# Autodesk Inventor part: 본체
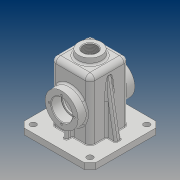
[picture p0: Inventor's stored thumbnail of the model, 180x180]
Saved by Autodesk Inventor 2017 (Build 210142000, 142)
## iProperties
Part Number: 본체
Material: 일반
Document SubType Name: Modeling
Designer: 20
Density: 1 g/cm^3
Appearance: 기본값
Mass: 292.115 g
Surface Area: 897.365 cm^2
Volume: 292.115 cm^3
Author: 20
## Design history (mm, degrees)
sketch "스케치1"
  geometry: L1 (-32.5, -32.5)-(32.5, -32.5); L2 (32.5, -32.5)-(32.5, 32.5); L3 (32.5, 32.5)-(-32.5, 32.5); L4 (-32.5, 32.5)-(-32.5, -32.5); L5 (-32.5, -32.5)-(32.5, 32.5); L6 (32.5, -32.5)-(-32.5, 32.5); 1 further point
  constraints: 12 end point, 2 midpoint, 2 parallel, 1 horizontal, 1 perpendicular
  dimensions: "d0" = 65 distance of L3.end L2.end; "d1" = 65 distance of L2.end L1.end
extrude "돌출1" new body sketch "스케치1" distance "d2" = 100; taper "d3" = 0 deg
fillet "모깎기1" dims "d4" = 8
fillet "모깎기2" dims "d5" = 8
feature "쉘1" dims "d6" = 5
sketch "스케치2"
  geometry: C1 r 20 at (0, 0); 1 further point
  constraints: 1 centre point, 1 coincident
  dimensions: "d7" = 40 diameter of C1
extrude "돌출2" join sketch "스케치2" distance "d8" = 10; taper "d9" = -5 deg
node "작업 평면1"
sketch "스케치4"
  geometry: C1 r 27.5 at (24.5, 45); 1 further point
  constraints: 1 centre point, 1 vertical alignment
  dimensions: "d14" = 55 diameter of C1; "d15" = 45 distance of C1.centre point (24.5, 0)
extrude "돌출4" join sketch "스케치4" stored distance "d16" = 10; taper "d17" = 0 deg
hole "구멍1" diameter "d20" = 30; stored, may be unused: countersink angle "d24" = 90 deg, drill point angle "d26" = 0 deg; dims "d18" = 10, "d19" = 10, "d21" = 6, "d22" = 35, "d23" = 17, "d25" = 20
sketch "스케치5"
  geometry: C1 r 27.5 at (0, 0) reference; 2 further points
  constraints: 1 vertical alignment
  dimensions: "d27" = 21 distance of C1.centre point (0, 21)
hole "구멍2" sketch "스케치5" at (0, 21) diameter "d28" = 3.242; stored, may be unused: countersink angle "d32" = 90 deg, drill point angle "d34" = 118 deg; dims "d29" = 8, "d30" = 4, "d31" = 17, "d33" = 10
sketch "스케치6"
  geometry: L1 (60, -60)-(-60, -60); L2 (-60, -60)-(-60, 60); L3 (-60, 60)-(60, 60); L4 (60, 60)-(60, -60); L5 (60, -60)-(-60, 60); L6 (-60, -60)-(60, 60); L7 (-27.5, -24.5)-(-27.5, 24.5) reference; L8 (24.5, -27.5)-(-24.5, -27.5) reference; L9 (27.5, 24.5)-(27.5, -24.5) reference; L10 (-24.5, 27.5)-(24.5, 27.5) reference; A1 r 3 centre (-24.5, -24.5) between (-27.5, -24.5) and (-24.5, -27.5) reference; A2 r 3 centre (24.5, -24.5) between (24.5, -27.5) and (27.5, -24.5) reference; A3 r 3 centre (24.5, 24.5) between (27.5, 24.5) and (24.5, 27.5) reference; A4 r 3 centre (-24.5, 24.5) between (-24.5, 27.5) and (-27.5, 24.5) reference; 1 further point
  constraints: 12 end point, 2 midpoint, 2 parallel, 1 horizontal, 1 perpendicular
  dimensions: "d38" = 120 distance of L2.end L3.end; "d39" = 120 distance of L1.end L2.end
extrude "돌출5" join sketch "스케치6" distance "d40" = 10; taper "d41" = 0 deg
chamfer "모따기1" distance "d42" = 10; stored, may be unused: second distance "d43" = 2, angle "d44" = 45 deg
sketch "스케치7"
  geometry: C1 r 5 at (-47.5, -47.5); 1 further point
  constraints: 1 centre point
  dimensions: "d45" = 10 diameter of C1; "d46" = 47.5 horizontal distance of C1.centre point (0, 0); "d47" = 47.5 horizontal distance of C1.centre point (0, 0)
extrude "돌출6" cut sketch "스케치7" distance "d48" = 10; taper "d49" = 0 deg
hole "구멍3" diameter "d58" = 22.835; stored, may be unused: countersink angle "d62" = 90 deg, drill point angle "d64" = 118 deg; dims "d56" = 10, "d57" = 10, "d59" = 25, "d60" = 4, "d61" = 17, "d63" = 25
sketch "스케치8"
  geometry: L1 (-47.5, 17.5)-(-32.5, 17.5) reference; L2 (-42.5, 17.5)-(-42.5, 0); L3 (-27.5, 92)-(-27.5, -10) reference; 1 further point
  constraints: 2 end point, 1 point on line, 1 vertical
  dimensions: "d65" = 15 distance between parallel lines of L3 L2
feature "리브1" sketch "스케치8" dims "d66" = 1, "d67" = 6, "d68" = 0, "d69" = 0, "d70" = 1, "d71" = 1
sketch "스케치9"
  geometry: L1 (-52.5, 0)-(-42.5, 0) reference; L2 (-48, 0)-(-42.71, 30); L3 (-60, 0)-(-60, -10) reference; 1 further point
  constraints: 2 end point, 1 point on line
  dimensions: "d72" = 12 distance from line of L3 L2.start; "d73" = 10 deg angle of L2 L3; "d74" = 30 vertical distance of L2.start L2.end
feature "리브2" sketch "스케치9" dims "d75" = 1, "d76" = 10, "d77" = 0, "d78" = 0, "d79" = 1, "d80" = 1
fillet "모깎기3" dims "d81" = 0.3
chamfer "모따기2" distance "d82" = 1; stored, may be unused: second distance "d83" = 2, angle "d84" = 45 deg
fillet "모깎기4" dims "d85" = 3
fillet "모깎기5" dims "d86" = 3
fillet "모깎기6" dims "d87" = 3
fillet "모깎기7" dims "d88" = 3
fillet "모깎기8" dims "d89" = 1
fillet "모깎기9" dims "d90" = 3
node "작업 평면2"
sketch "스케치10"
  geometry: L1 (43.625, -18)-(5.375, -18) reference; L2 (57, 0)-(57, 91) reference; 2 further points
  constraints: 1 other
  dimensions: "d92" = 26 distance from line of point (24.5, 8) L1; "d93" = 32.5 distance from line of L2 point (24.5, 8)
feature "엠보싱1" sketch "스케치10" dims "d94" = 0.5, "d95" = 0
node "솔리드1"
pattern_circular "원형 패턴1" dims angle "d36" = 360 deg
mirror "미러1"
pattern_linear "직사각형 패턴1" dims "d52" = 95, "d55" = 95
mirror "미러2"
mirror "미러3"
other parameters: "d13" = 15
